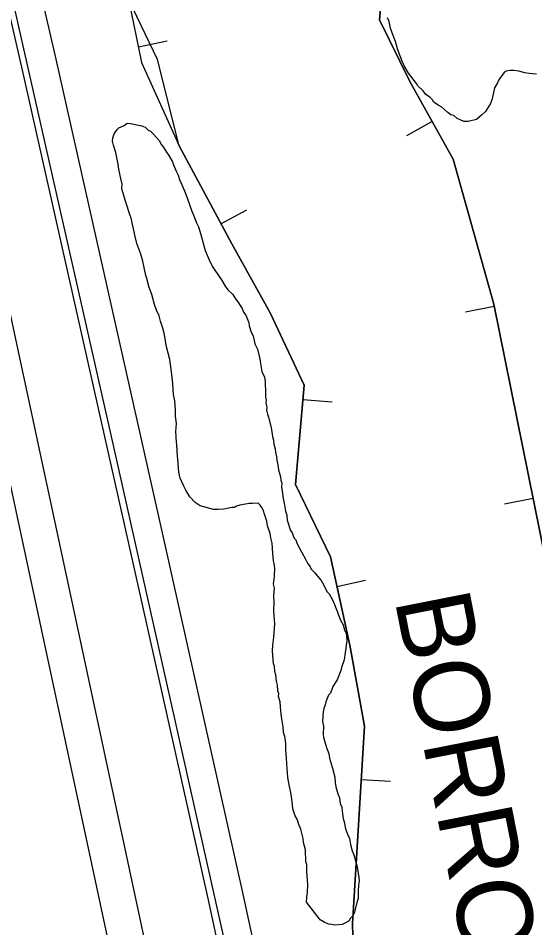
# Model space of a CAD drawing. Extents: x 3263578 to 3301413, y 764927 to 798602.
# Drawn here: x 3274651 to 3275091, y 791801 to 792575 of the extents above; entities that cross this region are included whole.
import ezdxf

# ---------------------------------------------------------------- set-up
doc = ezdxf.new("R2010")
doc.units = 0
for name, color, linetype in [('V-BORW-IDEN', 7, 'Continuous'), ('V-BORW-LINE', 7, 'Continuous'), ('V-LEVE-TOET', 7, 'Continuous'), ('V-ROAD-CNTR', 7, 'Continuous'), ('V-SITE-VEGE', 7, 'Continuous'), ('V-SURV-LINE', 7, 'Continuous')]:
    doc.layers.add(name, color=color, linetype=linetype)

msp = doc.modelspace()

# ---------------------------------------------------------------- linework, layer by layer
at = {"layer": 'V-BORW-LINE'}
for p, q in [((3274753.45, 792550.48), (3274777.93, 792555.54)), ((3275003.36, 792486.9), (3274981.55, 792474.69)), ((3274823.73, 792399.98), (3274845.76, 792411.8)), ((3275056.18, 792329.76), (3275031.68, 792324.79)), ((3274893.36, 792250.62), (3274918.27, 792248.5)), ((3275089.32, 792166.49), (3275064.82, 792161.52)), ((3274922.3, 792091.62), (3274946.71, 792097)), ((3274942.96, 791927.41), (3274967.92, 791925.9))]:
    msp.add_line(p, q, dxfattribs=at)
for points in [[(3275275.13, 791210.66), (3275179.76, 791757.75), (3275119.77, 792016.49), (3275055.79, 792331.66), (3275021.3, 792454.88), (3274984.32, 792520.89), (3274958.52, 792573.45), (3274965.06, 792647.98), (3274987.55, 792708.35), (3275017.65, 792773.95), (3275021.83, 792904.97), (3274994.29, 793017.93), (3274945.74, 793121.95), (3274888.34, 793200.25), (3274826.32, 793204.51), (3274784.59, 793302.06), (3274778.76, 793320.9), (3274727.47, 793451.22), (3274674.18, 793567.52), (3274649.13, 793794.35), (3274623.98, 793957.58), (3274632.85, 794016.04)], [(3274965.06, 792647.98), (3274958.52, 792573.45), (3274984.32, 792520.89), (3275021.3, 792454.88), (3275055.79, 792331.66), (3275119.77, 792016.49), (3275179.76, 791757.75), (3275275.13, 791210.66), (3275330.22, 790997.4), (3275381.34, 790982.81), (3275433.67, 790881.95), (3275487.61, 790746.75), (3275484.46, 790617.38), (3275463.15, 790576.09), (3275418.22, 790526.64)], [(3274745.04, 792591.15), (3274756.19, 792537.23), (3274788.14, 792466.28), (3274832.96, 792382.79), (3274865.56, 792324.31), (3274894.38, 792262.66), (3274887.21, 792178.16), (3274916.78, 792116.65), (3274933.29, 792041.71), (3274945.71, 791972.8), (3274935.54, 791804.69), (3274937.42, 791743.53), (3274996.68, 791645.61), (3274995.93, 791562.94), (3275010.57, 791520.83), (3275048.92, 791423.92), (3275068.41, 791340.98)], [(3275068.41, 791340.98), (3275048.92, 791423.92), (3275010.57, 791520.83), (3274995.93, 791562.94), (3274996.68, 791645.61), (3274937.42, 791743.53), (3274935.54, 791804.69), (3274945.71, 791972.8), (3274933.29, 792041.71), (3274916.78, 792116.65), (3274887.21, 792178.16), (3274894.38, 792262.66), (3274865.56, 792324.31), (3274832.96, 792382.79), (3274788.14, 792466.28), (3274769.66, 792539.58), (3274745.04, 792591.15)]]:
    msp.add_lwpolyline(points, dxfattribs=at)
at = {"layer": 'V-LEVE-TOET'}
msp.add_lwpolyline([(3274973.85, 791123.35), (3274899.09, 791474.39), (3274828.94, 791780.63), (3274730.13, 792221.62), (3274640.73, 792616.72), (3274571.67, 792950.56), (3274481.8, 793386.45), (3274351.94, 793983.31), (3274344.63, 794016.01)], dxfattribs=at)
at = {"layer": 'V-ROAD-CNTR'}
for points in [[(3274360.76, 794021.94), (3274379.51, 793936.59), (3274409.32, 793812.27), (3274430.08, 793703.87), (3274447.64, 793599.49), (3274488.47, 793442.14), (3274518.83, 793321.56), (3274536.83, 793258.48), (3274546.76, 793213.8), (3274555.58, 793152.77), (3274573.63, 793050.46), (3274602.36, 792904.6), (3274642.12, 792717.67), (3274683.22, 792539.82), (3274774.29, 792134.77), (3274842.46, 791830.06), (3274889.61, 791611.71), (3274934.89, 791415.75), (3274956.84, 791273.98)], [(3274331.46, 794015.5), (3274350.27, 793929.88), (3274379.99, 793805.94), (3274400.55, 793698.56), (3274418.28, 793593.22), (3274459.4, 793434.71), (3274489.85, 793313.78), (3274507.74, 793251.1), (3274517.23, 793208.39), (3274525.96, 793148.02), (3274544.13, 793044.96), (3274572.97, 792898.58), (3274612.83, 792711.17), (3274653.97, 792533.15), (3274745.02, 792128.2), (3274813.16, 791823.62), (3274860.33, 791605.17), (3274905.41, 791410.07), (3274927.31, 791268.63)]]:
    msp.add_lwpolyline(points, dxfattribs=at)
at = {"layer": 'V-SITE-VEGE'}
for p, q in [((3274966.74, 792572.04), (3274965.52, 792575.18)), ((3274967.94, 792566.39), (3274966.74, 792572.04)), ((3274969.77, 792561.37), (3274967.94, 792566.39)), ((3274972.21, 792555.09), (3274969.77, 792561.37)), ((3274974.04, 792548.81), (3274972.21, 792555.09)), ((3274977.7, 792538.76), (3274974.04, 792548.81)), ((3274979.53, 792534.36), (3274977.7, 792538.76)), ((3274983.23, 792528.07), (3274979.53, 792534.36)), ((3274990.03, 792519.24), (3274983.23, 792528.07)), ((3275062.7, 792526.08), (3275060.17, 792522.35)), ((3275064.6, 792528.57), (3275062.7, 792526.08)), ((3275066.49, 792529.8), (3275064.6, 792528.57)), ((3275069.63, 792530.4), (3275066.49, 792529.8)), ((3275072.76, 792530.37), (3275069.63, 792530.4)), ((3275077.13, 792529.7), (3275072.76, 792530.37)), ((3275082.13, 792528.4), (3275077.13, 792529.7)), ((3275085.88, 792527.74), (3275082.13, 792528.4)), ((3275092.13, 792527.06), (3275085.88, 792527.74)), ((3274991.27, 792517.35), (3274990.03, 792519.24)), ((3274995.61, 792512.93), (3274991.27, 792517.35)), ((3275058.89, 792519.85), (3275056.35, 792515.5)), ((3275060.17, 792522.35), (3275058.89, 792519.85)), ((3274998.08, 792509.78), (3274995.61, 792512.93)), ((3275001.81, 792507.24), (3274998.08, 792509.78)), ((3275056.35, 792515.5), (3275054.38, 792506.13)), ((3275003.68, 792505.35), (3275001.81, 792507.24)), ((3275004.91, 792503.46), (3275003.68, 792505.35)), ((3275008.64, 792500.92), (3275004.91, 792503.46)), ((3275011.75, 792499.01), (3275008.64, 792500.92)), ((3275053.1, 792502.38), (3275048.65, 792495.54)), ((3275054.38, 792506.13), (3275053.1, 792502.38)), ((3275016.72, 792494.58), (3275011.75, 792499.01)), ((3275019.21, 792492.68), (3275016.72, 792494.58)), ((3275048.65, 792495.54), (3275045.49, 792492.44)), ((3275021.7, 792492.04), (3275019.21, 792492.68)), ((3275024.81, 792489.5), (3275021.7, 792492.04)), ((3275027.3, 792488.23), (3275024.81, 792489.5)), ((3275030.42, 792486.94), (3275027.3, 792488.23)), ((3275034.17, 792486.91), (3275030.42, 792486.94)), ((3275041.08, 792488.73), (3275034.17, 792486.91)), ((3275045.49, 792492.44), (3275041.08, 792488.73))]:
    msp.add_line(p, q, dxfattribs=at)
for points in [[(3274732.3, 792466.84), (3274731.52, 792470.26), (3274731.68, 792473.15), (3274732.83, 792476.45), (3274735.44, 792480.17), (3274736.96, 792481.53), (3274741.42, 792483.69), (3274743.92, 792485.49), (3274746.8, 792485.32), (3274756.33, 792483.36), (3274759.16, 792482.24), (3274761.91, 792479.68), (3274763.78, 792478.61), (3274766.08, 792476.56), (3274771.53, 792470.48), (3274772.81, 792467.52), (3274774.62, 792465.49), (3274777.27, 792461.01), (3274779.51, 792457.99), (3274782.59, 792452.52), (3274783.42, 792450.07), (3274785.53, 792444.65), (3274787.27, 792441.18), (3274788.52, 792437.74), (3274792.8, 792427.87), (3274794.88, 792421.97), (3274799.08, 792410.66), (3274800.79, 792406.71), (3274802.88, 792400.82), (3274804.61, 792397.35), (3274806.67, 792390.97), (3274810.26, 792377.28), (3274813.68, 792369.39), (3274816.27, 792363.94), (3274818.49, 792360.45), (3274824.31, 792352.42), (3274827.39, 792346.95), (3274829.63, 792343.94), (3274833.74, 792339.86), (3274835.5, 792336.87), (3274838.66, 792332.84), (3274839.97, 792330.36), (3274841.75, 792327.85), (3274843.04, 792324.89), (3274844.83, 792322.38), (3274846.51, 792317.95), (3274847.37, 792315.98), (3274847.69, 792313.07), (3274849.32, 792307.68), (3274851.08, 792304.69), (3274852.64, 792297.86), (3274854.8, 792293.41), (3274856.75, 792285.11), (3274857.51, 792281.21), (3274858.58, 792274.41), (3274860.72, 792269.47), (3274861.47, 792265.58), (3274861.31, 792262.7), (3274861.58, 792258.83), (3274861.72, 792252.55), (3274862.06, 792250.13), (3274861.93, 792247.72), (3274862.68, 792243.83), (3274862.55, 792241.43), (3274863.33, 792238.01), (3274864.16, 792235.55), (3274866.56, 792226.75), (3274867.58, 792218.98), (3274868.39, 792216.05), (3274868.68, 792212.66), (3274869.91, 792208.74), (3274870.24, 792205.83), (3274870.98, 792201.93), (3274871.31, 792199.03), (3274872.03, 792194.65), (3274872.78, 792190.75), (3274874.38, 792184.88), (3274874.71, 792181.97), (3274875.53, 792179.52), (3274875.35, 792176.15), (3274876.05, 792171.3), (3274876.34, 792167.91), (3274877.49, 792162.55), (3274878.57, 792155.74), (3274879.83, 792152.3), (3274880.07, 792147.95), (3274882.95, 792139.12), (3274884.29, 792137.12), (3274885.12, 792134.66), (3274885.98, 792132.69), (3274887.34, 792131.17), (3274888.59, 792127.72), (3274896.05, 792114.31), (3274897.33, 792111.35), (3274899.58, 792108.33), (3274900.43, 792106.36), (3274903.64, 792103.29)], [(3274878.81, 791958.18), (3274878.16, 791963.99), (3274876.9, 791967.44), (3274876.69, 791972.27), (3274875.62, 791979.07), (3274874.87, 791982.97), (3274874.25, 791989.26), (3274874, 791993.61), (3274872.8, 791998.02), (3274872.93, 792000.42), (3274872.1, 792002.87), (3274871.89, 792007.7), (3274871.11, 792011.12), (3274870.44, 792016.46), (3274869.64, 792019.39), (3274869.39, 792023.74), (3274868.54, 792025.71), (3274867.71, 792036.84), (3274867.97, 792041.65), (3274868.82, 792048.35), (3274869.45, 792059.88), (3274868.86, 792066.66), (3274868.62, 792071), (3274869.01, 792078.21), (3274868.82, 792083.52), (3274869.19, 792090.24), (3274868.41, 792093.66), (3274869.26, 792100.36), (3274869.63, 792107.08), (3274868.88, 792110.98), (3274868.54, 792113.41), (3274867.92, 792119.71), (3274867.43, 792128.41), (3274866.23, 792132.81), (3274865.48, 792136.71), (3274863.42, 792143.08), (3274862.67, 792146.98), (3274861.46, 792151.38), (3274860.63, 792153.84), (3274859.81, 792156.29), (3274858.5, 792158.77), (3274857.16, 792160.77), (3274855.32, 792162.32), (3274850.49, 792162.1), (3274847.61, 792162.26), (3274844.67, 792161.46), (3274839.81, 792160.76), (3274836.88, 792159.96), (3274835.36, 792158.6), (3274832.96, 792158.73), (3274826.12, 792157.18), (3274821.29, 792156.96), (3274817.45, 792157.17), (3274806.05, 792160.2), (3274801.86, 792162.84), (3274797.32, 792167.91), (3274793.77, 792173.41), (3274792.03, 792176.88), (3274789.04, 792183.79), (3274787.86, 792188.67), (3274787.03, 792199.8), (3274786.68, 792202.22), (3274786.24, 792211.88), (3274785.9, 792214.31), (3274785.44, 792223.49), (3274785.81, 792230.22), (3274785.19, 792236.52), (3274785, 792241.83), (3274784.46, 792249.57), (3274783.31, 792254.93), (3274782.82, 792263.63), (3274782.18, 792269.45), (3274780.11, 792284.5), (3274777.33, 792295.25), (3274775.56, 792306.91), (3274774.35, 792311.31), (3274772.27, 792317.21), (3274771.07, 792321.61), (3274768.93, 792326.55), (3274767.27, 792331.46), (3274764.84, 792339.78), (3274762.75, 792345.68), (3274760.77, 792353.5), (3274759.94, 792355.95), (3274757.24, 792368.15), (3274755.63, 792374.02), (3274752.29, 792383.35), (3274750.68, 792389.23), (3274747.21, 792404.84), (3274745.52, 792409.27), (3274744.34, 792414.15), (3274742.26, 792420.04), (3274741.03, 792423.97), (3274739.42, 792429.83), (3274739.63, 792433.68), (3274738.46, 792438.56), (3274738.11, 792440.99), (3274736.95, 792446.35), (3274736.23, 792450.73), (3274734.36, 792460.47), (3274732.3, 792466.84)], [(3274903.64, 792103.29), (3274905.88, 792100.28), (3274909.06, 792096.73), (3274911.25, 792092.76), (3274913.84, 792087.31), (3274915.66, 792085.29), (3274918.3, 792080.8), (3274919.61, 792078.32), (3274920.46, 792076.35), (3274921.7, 792072.43), (3274922.55, 792070.45), (3274923.38, 792067.99), (3274925.52, 792063.06), (3274927.71, 792059.09), (3274928.91, 792054.69), (3274930.2, 792051.72), (3274930.55, 792049.3), (3274930.81, 792045.43), (3274930.12, 792041.61), (3274929.99, 792039.21), (3274929.3, 792035.39), (3274928.48, 792029.17), (3274926.19, 792022.55), (3274925.57, 792020.17), (3274922.72, 792012.14), (3274919.04, 792006.56), (3274916.81, 792000.9), (3274915.26, 791999.06), (3274913.02, 791993.4), (3274912.41, 791991.02), (3274911.27, 791987.71), (3274910.63, 791984.86), (3274910.18, 791976.69), (3274910.93, 791972.8), (3274910.56, 791966.07), (3274910.88, 791963.16), (3274913.74, 791953.85), (3274915.43, 791949.42), (3274916.18, 791945.52), (3274918.61, 791937.2), (3274920.59, 791929.38), (3274920.83, 791925.03), (3274921.58, 791921.14), (3274923.19, 791915.27), (3274924.45, 791911.82), (3274925.14, 791906.97), (3274926.43, 791904.01), (3274926.72, 791900.62), (3274927.82, 791894.29), (3274928.62, 791891.36), (3274929.75, 791885.51), (3274931.43, 791881.08), (3274933.14, 791877.14), (3274933.84, 791872.28), (3274935.47, 791866.89), (3274936.73, 791863.45), (3274939.54, 791853.17), (3274940.29, 791849.28), (3274940.98, 791844.42), (3274941.28, 791841.03), (3274940.62, 791837.7), (3274940.33, 791832.41), (3274940.46, 791826.14), (3274939.32, 791822.83), (3274937.43, 791814.74), (3274935.8, 791811.46), (3274933.75, 791809.16), (3274932.68, 791807.3), (3274929.69, 791805.53), (3274926.73, 791804.25), (3274920.44, 791803.63), (3274918.06, 791804.24), (3274915.18, 791804.4), (3274911.41, 791806.05), (3274908.16, 791808.16), (3274907.25, 791809.17), (3274896.46, 791823.26), (3274896.69, 791827.58), (3274897.38, 791831.4), (3274897.75, 791838.12), (3274896.92, 791849.25), (3274896.76, 791855.04), (3274895.93, 791857.49), (3274895.52, 791867.64), (3274893.94, 791873.99), (3274893.64, 791877.38), (3274892.44, 791881.78), (3274891.66, 791885.19), (3274889.95, 791889.14), (3274888.72, 791893.07), (3274886.99, 791896.53), (3274884.9, 791902.43), (3274884.6, 791905.82), (3274883.91, 791910.68), (3274883.26, 791916.49), (3274882.09, 791921.37), (3274880.59, 791929.17), (3274880.02, 791936.43), (3274879.56, 791945.61), (3274879, 791952.86), (3274878.81, 791958.18)]]:
    msp.add_lwpolyline(points, dxfattribs=at)
at = {"layer": 'V-SURV-LINE'}
for points in [[(3274771.28, 791588.79), (3274250.31, 794016.01)], [(3274280.99, 794016.01), (3274800.61, 791595.1)]]:
    msp.add_lwpolyline(points, dxfattribs=at)

# ---------------------------------------------------------------- texts
at = {"layer": 'V-BORW-IDEN'}
msp.add_text('BORROW PIT', height=64, rotation=281.10642, dxfattribs=at).set_placement((3274971.32, 792080.57))

doc.saveas('drawing.dxf')
